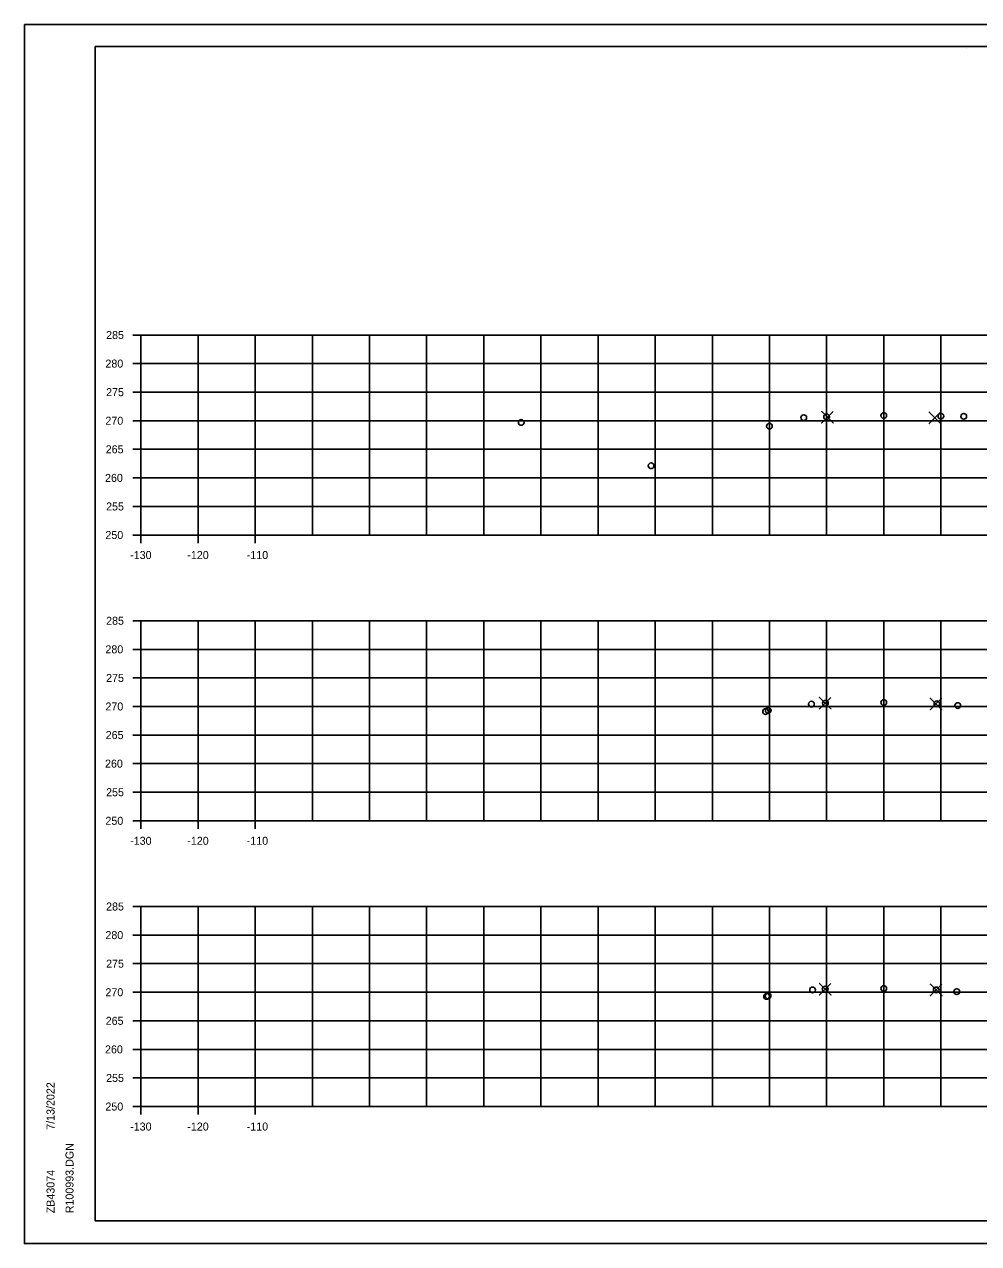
# Model space of a CAD drawing. Extents: x 4667 to 1632277, y -2100 to 724501.
# Drawn here: x 5969.1 to 6136.1, y -1963.8 to -1750.4 of the extents above; entities that cross this region are included whole.
import ezdxf

# ---------------------------------------------------------------- set-up
doc = ezdxf.new("R2010")
doc.units = 0
for name, color, linetype in [('R_Axis', 7, 'Continuous'), ('R_Axis Annot', 7, 'Continuous'), ('R_Grid', 7, 'Continuous'), ('R_No Plot', 7, 'Continuous')]:
    doc.layers.add(name, color=color, linetype=linetype)

msp = doc.modelspace()

# ---------------------------------------------------------------- linework, layer by layer
at = {"layer": 'R_Axis'}
for p, q in [((5988.12, -1804.78), (5989.52, -1804.78)), ((5989.52, -1839.78), (5989.52, -1804.78)), ((5988.12, -1809.78), (5989.52, -1809.78)), ((5988.12, -1814.78), (5989.52, -1814.78)), ((5988.12, -1819.78), (5989.52, -1819.78)), ((5988.12, -1824.78), (5989.52, -1824.78)), ((5988.12, -1829.78), (5989.52, -1829.78)), ((5988.12, -1834.78), (5989.52, -1834.78)), ((5988.12, -1839.78), (5989.52, -1839.78)), ((5989.52, -1841.18), (5989.52, -1839.78)), ((5999.52, -1841.18), (5999.52, -1839.78)), ((6009.52, -1841.18), (6009.52, -1839.78)), ((5988.12, -1854.78), (5989.52, -1854.78)), ((5989.52, -1889.78), (5989.52, -1854.78)), ((5988.12, -1859.78), (5989.52, -1859.78)), ((5988.12, -1864.78), (5989.52, -1864.78)), ((5988.12, -1869.78), (5989.52, -1869.78)), ((5988.12, -1874.78), (5989.52, -1874.78)), ((5988.12, -1879.78), (5989.52, -1879.78)), ((5988.12, -1884.78), (5989.52, -1884.78)), ((5988.12, -1889.78), (5989.52, -1889.78)), ((5989.52, -1891.18), (5989.52, -1889.78)), ((5999.52, -1891.18), (5999.52, -1889.78)), ((6009.52, -1891.18), (6009.52, -1889.78)), ((5988.12, -1904.78), (5989.52, -1904.78)), ((5989.52, -1939.78), (5989.52, -1904.78)), ((5988.12, -1909.78), (5989.52, -1909.78)), ((5988.12, -1914.78), (5989.52, -1914.78)), ((5988.12, -1919.78), (5989.52, -1919.78)), ((5988.12, -1924.78), (5989.52, -1924.78)), ((5988.12, -1929.78), (5989.52, -1929.78)), ((5988.12, -1934.78), (5989.52, -1934.78)), ((5988.12, -1939.78), (5989.52, -1939.78)), ((5989.52, -1941.18), (5989.52, -1939.78)), ((5999.52, -1941.18), (5999.52, -1939.78)), ((6009.52, -1941.18), (6009.52, -1939.78))]:
    msp.add_line(p, q, dxfattribs=at)
at = {"layer": 'R_Grid'}
for p, q in [((5989.52, -1804.78), (6289.52, -1804.78)), ((5989.52, -1839.78), (5989.52, -1804.78)), ((5999.52, -1839.78), (5999.52, -1804.78)), ((6009.52, -1839.78), (6009.52, -1804.78)), ((6019.52, -1839.78), (6019.52, -1804.78)), ((6029.52, -1839.78), (6029.52, -1804.78)), ((6039.52, -1839.78), (6039.52, -1804.78)), ((6049.52, -1839.78), (6049.52, -1804.78)), ((6059.52, -1839.78), (6059.52, -1804.78)), ((6069.52, -1839.78), (6069.52, -1804.78)), ((6079.52, -1839.78), (6079.52, -1804.78)), ((6089.52, -1839.78), (6089.52, -1804.78)), ((6099.52, -1839.78), (6099.52, -1804.78)), ((6109.52, -1839.78), (6109.52, -1804.78)), ((6119.52, -1839.78), (6119.52, -1804.78)), ((6129.52, -1839.78), (6129.52, -1804.78)), ((5989.52, -1809.78), (6289.52, -1809.78)), ((5989.52, -1814.78), (6289.52, -1814.78)), ((5989.52, -1819.78), (6289.52, -1819.78)), ((5989.52, -1824.78), (6289.52, -1824.78)), ((5989.52, -1829.78), (6289.52, -1829.78)), ((5989.52, -1834.78), (6289.52, -1834.78)), ((5989.52, -1839.78), (6289.52, -1839.78)), ((5989.52, -1854.78), (6289.52, -1854.78)), ((5989.52, -1889.78), (5989.52, -1854.78)), ((5999.52, -1889.78), (5999.52, -1854.78)), ((6009.52, -1889.78), (6009.52, -1854.78)), ((6019.52, -1889.78), (6019.52, -1854.78)), ((6029.52, -1889.78), (6029.52, -1854.78)), ((6039.52, -1889.78), (6039.52, -1854.78)), ((6049.52, -1889.78), (6049.52, -1854.78)), ((6059.52, -1889.78), (6059.52, -1854.78)), ((6069.52, -1889.78), (6069.52, -1854.78)), ((6079.52, -1889.78), (6079.52, -1854.78)), ((6089.52, -1889.78), (6089.52, -1854.78)), ((6099.52, -1889.78), (6099.52, -1854.78)), ((6109.52, -1889.78), (6109.52, -1854.78)), ((6119.52, -1889.78), (6119.52, -1854.78)), ((6129.52, -1889.78), (6129.52, -1854.78)), ((5989.52, -1859.78), (6289.52, -1859.78)), ((5989.52, -1864.78), (6289.52, -1864.78)), ((5989.52, -1869.78), (6289.52, -1869.78)), ((5989.52, -1874.78), (6289.52, -1874.78)), ((5989.52, -1879.78), (6289.52, -1879.78)), ((5989.52, -1884.78), (6289.52, -1884.78)), ((5989.52, -1889.78), (6289.52, -1889.78)), ((5989.52, -1904.78), (6289.52, -1904.78)), ((5989.52, -1939.78), (5989.52, -1904.78)), ((5999.52, -1939.78), (5999.52, -1904.78)), ((6009.52, -1939.78), (6009.52, -1904.78)), ((6019.52, -1939.78), (6019.52, -1904.78)), ((6029.52, -1939.78), (6029.52, -1904.78)), ((6039.52, -1939.78), (6039.52, -1904.78)), ((6049.52, -1939.78), (6049.52, -1904.78)), ((6059.52, -1939.78), (6059.52, -1904.78)), ((6069.52, -1939.78), (6069.52, -1904.78)), ((6079.52, -1939.78), (6079.52, -1904.78)), ((6089.52, -1939.78), (6089.52, -1904.78)), ((6099.52, -1939.78), (6099.52, -1904.78)), ((6109.52, -1939.78), (6109.52, -1904.78)), ((6119.52, -1939.78), (6119.52, -1904.78)), ((6129.52, -1939.78), (6129.52, -1904.78)), ((5989.52, -1909.78), (6289.52, -1909.78)), ((5989.52, -1914.78), (6289.52, -1914.78)), ((5989.52, -1919.78), (6289.52, -1919.78)), ((5989.52, -1924.78), (6289.52, -1924.78)), ((5989.52, -1929.78), (6289.52, -1929.78)), ((5989.52, -1934.78), (6289.52, -1934.78)), ((5989.52, -1939.78), (6289.52, -1939.78))]:
    msp.add_line(p, q, dxfattribs=at)
at = {"layer": 'R_No Plot'}
for p, q in [((5969.12, -1750.43), (6302.46, -1750.43)), ((5981.52, -1754.32), (6297.7, -1754.32)), ((5981.52, -1959.78), (5981.52, -1754.32)), ((6134.04, -1754.58), (6134.04, -1754.58)), ((6134.04, -1754.58), (6134.04, -1754.58)), ((5981.52, -1959.78), (5981.52, -1959.78)), ((6297.7, -1959.78), (5981.52, -1959.78)), ((5969.12, -1963.76), (6302.46, -1963.76))]:
    msp.add_line(p, q, dxfattribs=at)
for points in [[(5969.12, -1750.43), (6302.46, -1750.43), (6302.46, -1963.77), (5969.12, -1963.77)], [(6215.44, -1754.32), (6215.44, -1764.2), (6251.18, -1764.2), (6251.18, -1767.12), (6274.38, -1767.12), (6274.38, -1791.45), (6297.7, -1791.45), (6297.7, -1959.78), (5981.52, -1959.78), (5981.52, -1754.32)]]:
    msp.add_lwpolyline(points, close=True, dxfattribs=at)
for points in [[(6109.66, -1819.17), (6108.66, -1818.17), (6109.66, -1819.17), (6108.66, -1820.17), (6109.66, -1819.17), (6110.66, -1820.17), (6109.66, -1819.17), (6110.66, -1818.17)], [(6128.48, -1819.27), (6127.48, -1818.27), (6128.48, -1819.27), (6127.48, -1820.27), (6128.48, -1819.27), (6129.48, -1820.27), (6128.48, -1819.27), (6129.48, -1818.27)], [(6109.27, -1869.19), (6108.27, -1868.19), (6109.27, -1869.19), (6108.27, -1870.19), (6109.27, -1869.19), (6110.27, -1870.19), (6109.27, -1869.19), (6110.27, -1868.19)], [(6128.66, -1869.34), (6127.66, -1868.34), (6128.66, -1869.34), (6127.66, -1870.34), (6128.66, -1869.34), (6129.66, -1870.34), (6128.66, -1869.34), (6129.66, -1868.34)], [(6109.28, -1919.24), (6108.28, -1918.24), (6109.28, -1919.24), (6108.28, -1920.24), (6109.28, -1919.24), (6110.28, -1920.24), (6109.28, -1919.24), (6110.28, -1918.24)], [(6128.69, -1919.37), (6127.69, -1918.37), (6128.69, -1919.37), (6127.69, -1920.37), (6128.69, -1919.37), (6129.69, -1920.37), (6128.69, -1919.37), (6129.69, -1918.37)]]:
    msp.add_lwpolyline(points, dxfattribs=at)
for centre in [(6056.08, -1820.07), (6105.52, -1819.24), (6109.52, -1819.08), (6119.52, -1818.88), (6129.52, -1818.97), (6133.52, -1819.01), (6099.52, -1820.74), (6078.8, -1827.65), (6109.31, -1869.21), (6119.52, -1869.09), (6128.82, -1869.32), (6098.83, -1870.66), (6099.31, -1870.5), (6106.86, -1869.36), (6132.48, -1869.62), (6099.01, -1920.51), (6099.27, -1920.42), (6107.07, -1919.38), (6109.27, -1919.24), (6119.52, -1919.12), (6128.7, -1919.37), (6132.3, -1919.68)]:
    msp.add_circle(centre, 0.5, dxfattribs=at)

# ---------------------------------------------------------------- texts
at = {"layer": 'R_Axis Annot'}
for s, p in [('285', (5983.42, -1805.48)), ('280', (5983.3, -1810.48)), ('275', (5983.42, -1815.48)), ('270', (5983.3, -1820.48)), ('265', (5983.35, -1825.48)), ('260', (5983.23, -1830.48)), ('255', (5983.42, -1835.48)), ('250', (5983.3, -1840.48)), ('-130', (5987.63, -1843.98)), ('-120', (5997.63, -1843.98)), ('-110', (6008.03, -1843.98)), ('285', (5983.42, -1855.48)), ('280', (5983.3, -1860.48)), ('275', (5983.42, -1865.48)), ('270', (5983.3, -1870.48)), ('265', (5983.35, -1875.48)), ('260', (5983.23, -1880.48)), ('255', (5983.42, -1885.48)), ('250', (5983.3, -1890.48)), ('-130', (5987.63, -1893.98)), ('-120', (5997.63, -1893.98)), ('-110', (6008.03, -1893.98)), ('285', (5983.42, -1905.48)), ('280', (5983.3, -1910.48)), ('275', (5983.42, -1915.48)), ('270', (5983.3, -1920.48)), ('265', (5983.35, -1925.48)), ('260', (5983.23, -1930.48)), ('255', (5983.42, -1935.48)), ('250', (5983.3, -1940.48)), ('-130', (5987.63, -1943.98)), ('-120', (5997.63, -1943.98)), ('-110', (6008.03, -1943.98))]:
    msp.add_text(s, height=1.4, dxfattribs=at).set_placement(p)
at = {"layer": 'R_No Plot'}
for s, p in [('7/13/2022', (5974.39, -1943.85)), ('R100993.DGN', (5977.72, -1958.46)), ('ZB43074', (5974.39, -1958.46))]:
    msp.add_text(s, height=1.4, rotation=90, dxfattribs=at).set_placement(p)

doc.saveas('drawing.dxf')
